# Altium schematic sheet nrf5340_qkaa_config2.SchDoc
size A3; BoardTitle: nRF5340-QKAA Reference Layout - Config 2; Organization: Nordic Semiconductor; DocumentNumber: 1; Revision: 1.2; SheetNumber: 1; SheetTotal: 1; DrawnBy: RUBR/GETR/ERSA; DocumentSize: A3; RefLayoutTitle: Reference Layout Config. 2: VDD supply, DCDC, USB, NFC; Device: nRF5340-QKAA; Classification: PUBLIC
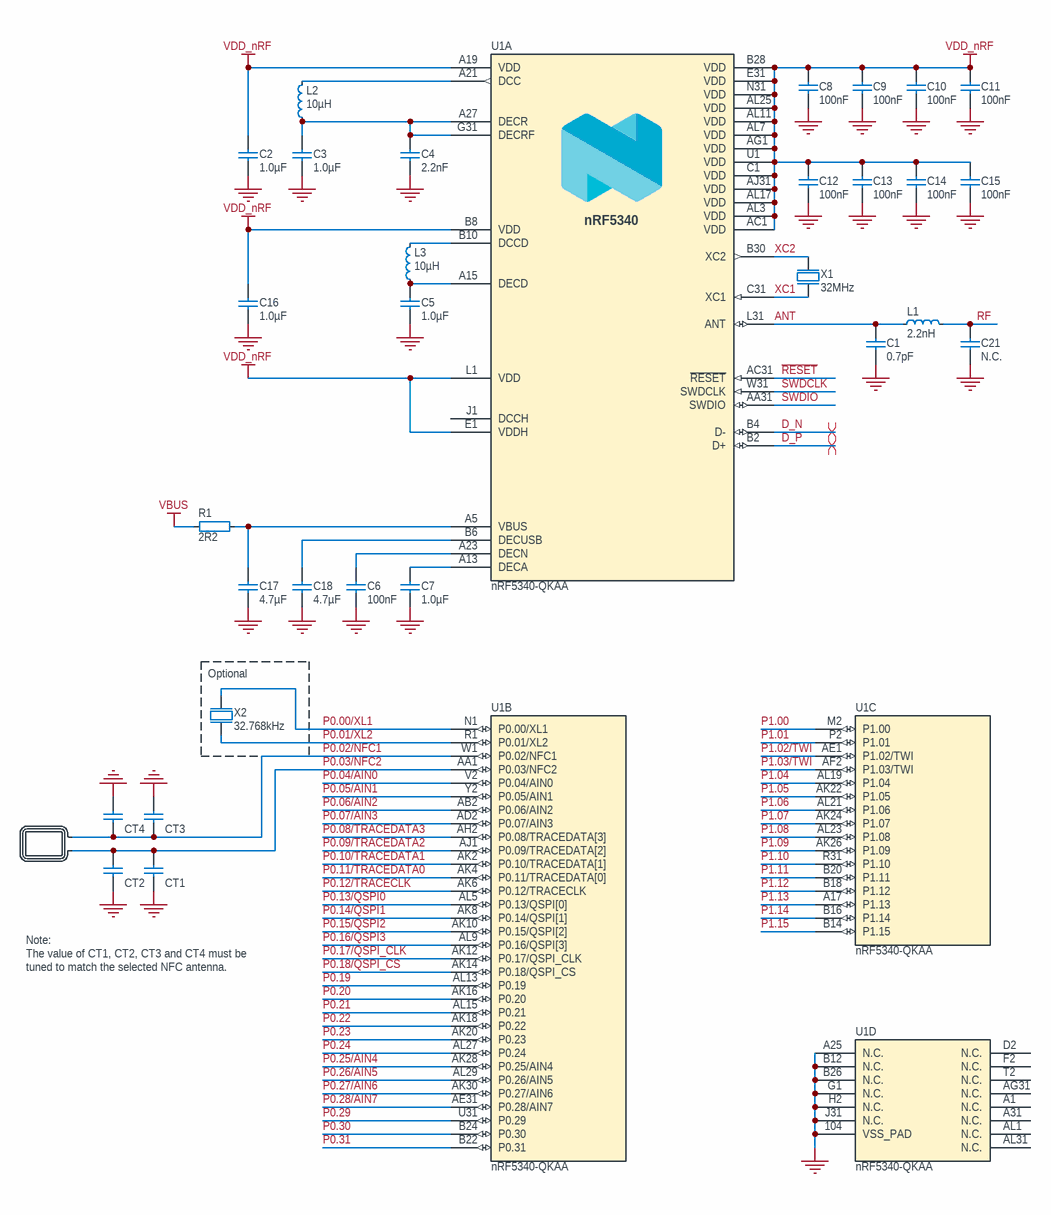
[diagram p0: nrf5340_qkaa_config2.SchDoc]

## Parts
A1  NFC Antenna  [TP_2x1mm_TH]  (value not drawn)  (no BOM)
C1  0.7pF  [CAPC0603X03L_C]
C2  1.0µF  [CAPC1005X04L]
C3  1.0µF  [CAPC1005X04L]
C4  2.2nF  [CAPC0603X03L_C]
C5  1.0µF  [CAPC1005X04L]
C6  100nF  [CAPC0603X03L_C]
C7  1.0µF  [CAPC1005X04L]
C8  100nF  [CAPC0603X03L_C]
C9  100nF  [CAPC0603X03L_C]
C10  100nF  [CAPC0603X03L_C]
C11  100nF  [CAPC0603X03L_C]
C12  100nF  [CAPC0603X03L_C]
C13  100nF  [CAPC0603X03L_C]
C14  100nF  [CAPC0603X03L_C]
C15  100nF  [CAPC0603X03L_C]
C16  1.0µF  [CAPC1005X04L]
C17  4.7µF  [CAPC1608X06L]
C18  4.7µF  [CAPC1608X06L]
C21  N.C.  [CAPC0603X03L_C_NC]
CT1  Antenna dependent  [CAPC0603X03L_C]  (value not drawn)
CT2  Antenna dependent  [CAPC0603X03L_C]  (value not drawn)
CT3  Antenna dependent  [CAPC0603X03L_C]  (value not drawn)
CT4  Antenna dependent  [CAPC0603X03L_C]  (value not drawn)
L1  2.2nH  [INDC0603X03L_C]
L2  10µH  [INDC1608X06L]
L3  10µH  [INDC1608X06L]
R1  2R2  [RESC0603X03L_C]
U1  nRF5340-QKAA  [AQFN40P700X700X85_HS-99N]  (parts A,B,C,D of 4)
X1  32MHz  [BT-XTAL_2016]
X2  32.768kHz  [XTAL_2012]

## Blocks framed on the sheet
Optional: X2

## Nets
GND: C1.1 C2.2 C3.1 C4.2 C5.1 C6.2 C7.1 C8.2 C9.2 C10.2 C11.2 C12.2 C13.2 C14.2 C15.2 C16.1 C17.2 C18.2 C21.1 CT1.2 CT2.2 CT3.1 CT4.1 U1.104(VSS_PAD) U1.A25(N.C.) U1.B12(N.C.) U1.B26(N.C.) U1.G1(N.C.) U1.H2(N.C.) U1.J31(N.C.) X1.2(GND) X1.4(GND)
VBUS: R1.1
VDD_nRF: C2.1 C8.1 C9.1 C10.1 C11.1 C12.1 C13.1 C14.1 C15.1 C16.2 U1.A19(VDD) U1.AC1(VDD) U1.AG1(VDD) U1.AJ31(VDD) U1.AL3(VDD) U1.AL7(VDD) U1.AL11(VDD) U1.AL17(VDD) U1.AL25(VDD) U1.B8(VDD) U1.B28(VDD) U1.C1(VDD) U1.E1(VDDH) U1.E31(VDD) U1.L1(VDD) U1.N31(VDD) U1.U1(VDD)
ANT: C1.2 L1.2 U1.L31(ANT)
D_N: U1.B4(D-)
D_P: U1.B2(D+)
P0.00/XL1: U1.N1(P0.00/XL1) X2.1(inp)
P0.01/XL2: U1.R1(P0.01/XL2) X2.2(out)
P0.02/NFC1: A1.1 CT3.2 CT4.2 U1.W1(P0.02/NFC1)
P0.03/NFC2: A1.2 CT1.1 CT2.1 U1.AA1(P0.03/NFC2)
P0.04/AIN0: U1.V2(P0.04/AIN0)
P0.05/AIN1: U1.Y2(P0.05/AIN1)
P0.06/AIN2: U1.AB2(P0.06/AIN2)
P0.07/AIN3: U1.AD2(P0.07/AIN3)
P0.08/TRACEDATA3: U1.AH2(P0.08/TRACEDATA[3])
P0.09/TRACEDATA2: U1.AJ1(P0.09/TRACEDATA[2])
P0.10/TRACEDATA1: U1.AK2(P0.10/TRACEDATA[1])
P0.11/TRACEDATA0: U1.AK4(P0.11/TRACEDATA[0])
P0.12/TRACECLK: U1.AK6(P0.12/TRACECLK)
P0.13/QSPI0: U1.AL5(P0.13/QSPI[0])
P0.14/QSPI1: U1.AK8(P0.14/QSPI[1])
P0.15/QSPI2: U1.AK10(P0.15/QSPI[2])
P0.16/QSPI3: U1.AL9(P0.16/QSPI[3])
P0.17/QSPI_CLK: U1.AK12(P0.17/QSPI_CLK)
P0.18/QSPI_CS: U1.AK14(P0.18/QSPI_CS)
P0.19: U1.AL13(P0.19)
P0.20: U1.AK16(P0.20)
P0.21: U1.AL15(P0.21)
P0.22: U1.AK18(P0.22)
P0.23: U1.AK20(P0.23)
P0.24: U1.AL27(P0.24)
P0.25/AIN4: U1.AK28(P0.25/AIN4)
P0.26/AIN5: U1.AL29(P0.26/AIN5)
P0.27/AIN6: U1.AK30(P0.27/AIN6)
P0.28/AIN7: U1.AE31(P0.28/AIN7)
P0.29: U1.U31(P0.29)
P0.30: U1.B24(P0.30)
P0.31: U1.B22(P0.31)
P1.00: U1.M2(P1.00)
P1.01: U1.P2(P1.01)
P1.02/TWI: U1.AE1(P1.02/TWI)
P1.03/TWI: U1.AF2(P1.03/TWI)
P1.04: U1.AL19(P1.04)
P1.05: U1.AK22(P1.05)
P1.06: U1.AL21(P1.06)
P1.07: U1.AK24(P1.07)
P1.08: U1.AL23(P1.08)
P1.09: U1.AK26(P1.09)
P1.10: U1.R31(P1.10)
P1.11: U1.B20(P1.11)
P1.12: U1.B18(P1.12)
P1.13: U1.A17(P1.13)
P1.14: U1.B16(P1.14)
P1.15: U1.B14(P1.15)
~{RESET}: U1.AC31(~{RESET})
RF: C21.2 L1.1
SWDCLK: U1.W31(SWDCLK)
SWDIO: U1.AA31(SWDIO)
XC1: U1.C31(XC1) X1.1(inp)
XC2: U1.B30(XC2) X1.3(out)
NetC3_2: C3.2 C4.1 L2.1 U1.A27(DECR) U1.G31(DECRF)
NetC5_2: C5.2 L3.1 U1.A15(DECD)
NetC6_1: C6.1 U1.A23(DECN)
NetC7_2: C7.2 U1.A13(DECA)
NetC17_1: C17.1 R1.2 U1.A5(VBUS)
NetC18_1: C18.1 U1.B6(DECUSB)
NetL2_2: L2.2 U1.A21(DCC)
NetL3_2: L3.2 U1.B10(DCCD)

Not connected (* = marked no-connect by the designer): U1 A1(N.C.) A31(N.C.) AG31(N.C.) AL1(N.C.) AL31(N.C.) D2(N.C.) F2(N.C.) J1(DCCH) T2(N.C.)

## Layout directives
differential pair: D_N, D_P

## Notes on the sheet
- Note:
  The value of CT1, CT2, CT3 and CT4 must be tuned to match the selected NFC antenna.

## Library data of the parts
A1 = NFC_ANT_TP: Pad Count: 2
C1 = C0201-0.7p: Capacitor, NP0, ±0.05pF; Pad Count: 2
C2 C3 C5 C7 C16 = C0402-1µ0-10V-X7S-GRM155C71A105KE11: Capacitor, X7S, ±10%; Pad Count: 2
C4 = C0201-2n2: Capacitor, X7R, ±10%; Pad Count: 2
C6 C8-C15 = C0201-100n-16V-X7S: Capacitor, X7S, ±10%; Pad Count: 2
C17 = C0603-4µ7-10V-X7S: Capacitor, X7S, ±10%; Pad Count: 2
C18 = C0603-4µ7-6.3V-X7R: Capacitor, X7R, ±10%; Pad Count: 2
C21 = C0201-N.C.: Not mounted; Assembly: Not mounted; Pad Count: 2
CT1-CT4 = C0201-TBD: Capacitor, NP0, ±5%; Pad Count: 2
L1 = L0201-2n2: High frequency chip inductor, ±5%; Pad Count: 2
L2 L3 = L0603-10µ: Chip Inductor, IDC,min = 50 mA, ±20%; Pad Count: 2
R1 = R0201-2R2: Resistor, ±1%, 0.05W; Pad Count: 2
U1 = nRF5340-QKAA: Multi-protocol Bluetooth Low Energy, IEEE 802.15.4, ANT and 2.4GHz proprietary system-on-chip; Pad Count: 98
X1 = XTAL_SMD2016_32MHz_8pF_General: XTAL SMD 2016, 32MHz, Cl=8pF, Total Tol: ±30ppm; Pad Count: 4
X2 = XTAL_SMD2012_32.768kHz_9pF_General: XTAL SMD 2012, 32.768kHz, Cl=9pF, Total Tol: ±50ppm; Pad Count: 2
